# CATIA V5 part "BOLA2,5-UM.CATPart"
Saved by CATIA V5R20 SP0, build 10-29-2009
Part number: BOLA2,5-UM
Revision: ANY
Definition: UNKNOWN
Nomenclature: BOLA2,5-UM
Source: Unknown
Bounding box of the stored display mesh (mm): x -1.25 to 1.25, y -1.25 to 1.25, z -1.25 to 1.25
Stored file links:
  C:\Users\Utente\Desktop\IO LAVORO\3D X SITO CF\X SITO\3D files UM\UM043642 PRODUCT\BOLA2,5-UM.CATPart
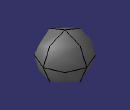
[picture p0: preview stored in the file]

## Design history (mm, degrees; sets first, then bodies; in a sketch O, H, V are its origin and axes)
Body1 "Revolución6" (main body)
  Solid1: solid without history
